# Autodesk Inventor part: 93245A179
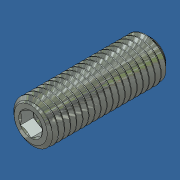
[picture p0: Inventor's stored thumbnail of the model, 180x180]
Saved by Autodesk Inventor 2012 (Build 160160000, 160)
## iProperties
Created: 2015-01
Part Number: 93245A179
Material: Steel
Document SubType Name: Modeling
Designer: Admin
Density: 7.85 g/cm^3
Mass: 24.3104 g
Surface Area: 22.6928 cm^2
Volume: 3.09687 cm^3
Translation Standard: STEP AP203
FileName: 93245A179.step
PreProcessor: SolidWorks 2010
PostProcessor: Build: 160, Release: 2012 RTM - Date: Tue 03/01/2011
Sent Units: millimeter
Uncertainty: 1e-05
Author: Admin
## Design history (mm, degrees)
feature "Base1"
body "Solid1"
